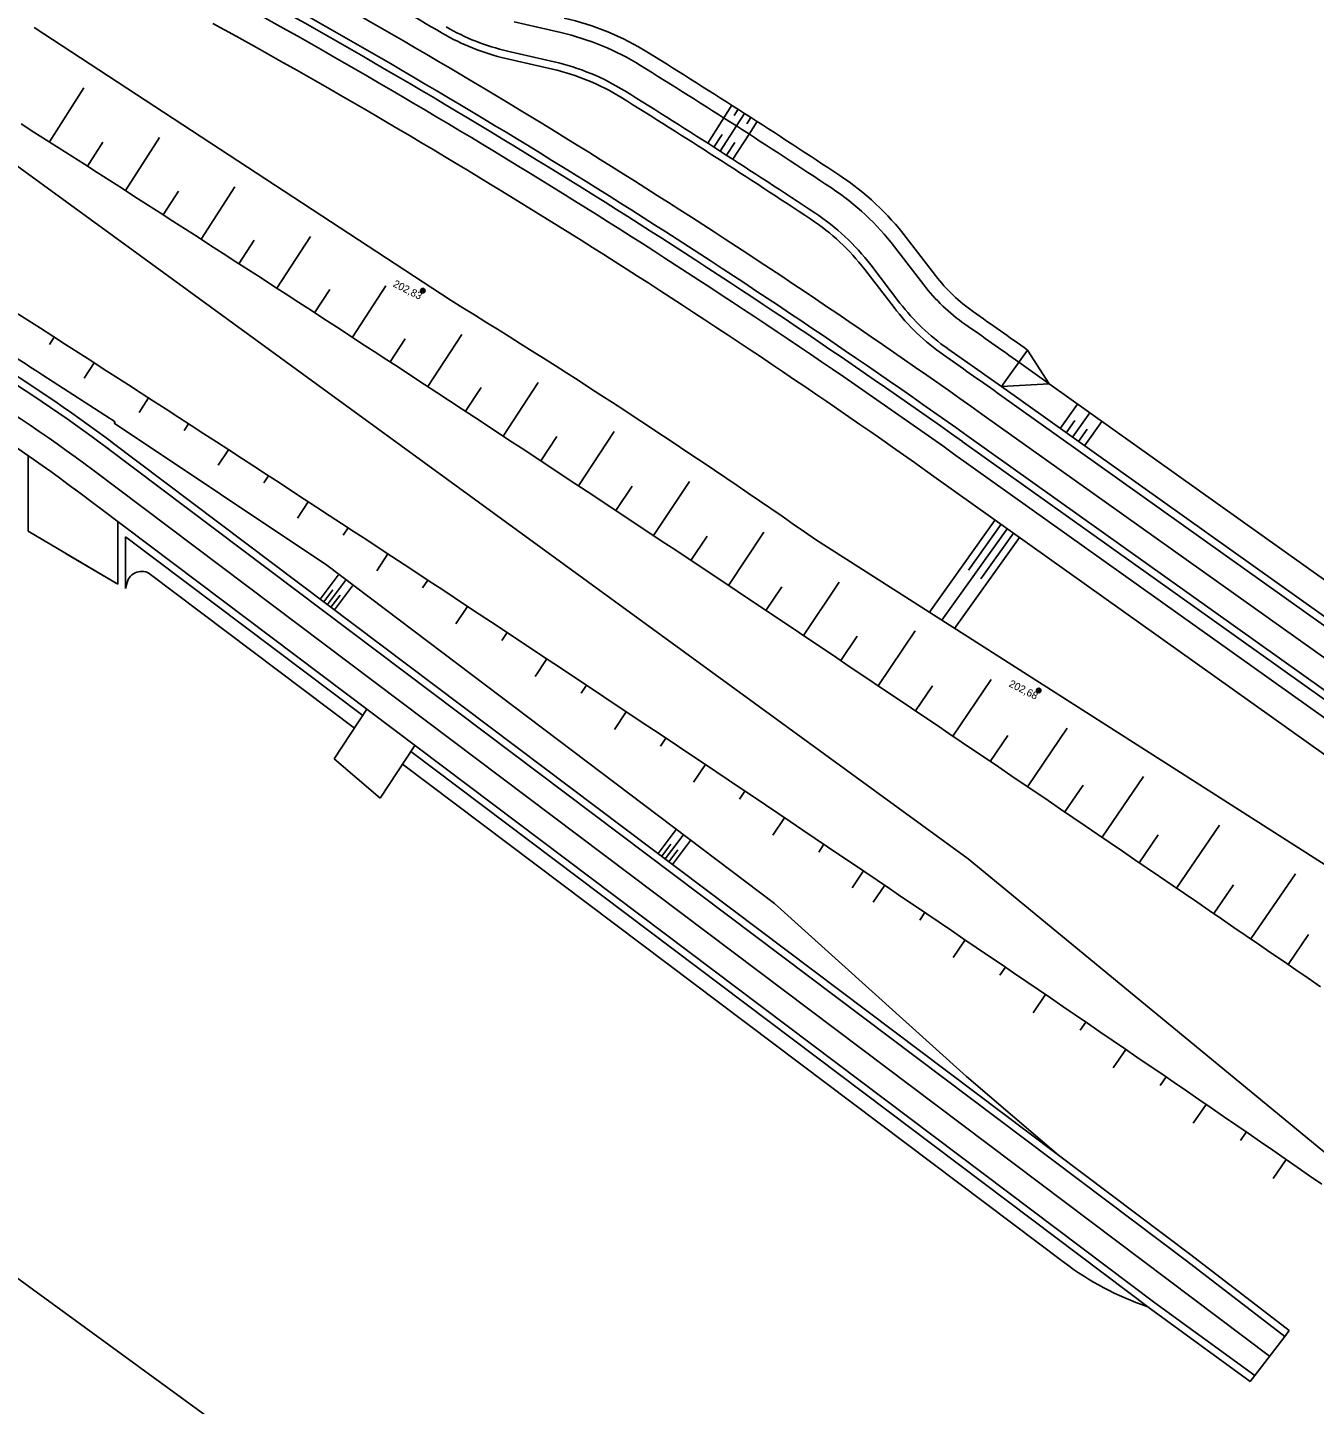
# Model space of a CAD drawing. Extents: x -551750 to -547457, y -1150683 to -1148508.
# Drawn here: x -550268.9 to -550183, y -1149131.6 to -1149039.7 of the extents above; entities that cross this region are included whole.
import ezdxf

# ---------------------------------------------------------------- set-up
doc = ezdxf.new("R2010")
doc.units = 0
for name, color, linetype in [('SO221815_VYSKOPIS', 7, 'Continuous'), ('u_ochranne_pasmo_CD', 7, 'Continuous'), ('u_trat navrh', 7, 'Continuous')]:
    doc.layers.add(name, color=color, linetype=linetype)

# ---------------------------------------------------------------- blocks, each defined once
blk = doc.blocks.new('SO221824_VYSKOPIS')
at = {"layer": 'SO221815_VYSKOPIS'}
for p, q in [((0.123, -0.085), (-0.123, 0.085)), ((0.086, 0.123), (-0.086, -0.123)), ((0.086, 0.123), (0, 0)), ((0, 0), (0.123, -0.085))]:
    blk.add_line(p, q, dxfattribs=at)
blk.add_lwpolyline([(-0.086, -0.123), (0, 0), (-0.123, 0.085)], dxfattribs=at)
blk.add_circle((0, 0), 0.15, dxfattribs=at)
for start, end in [(145.36204, 235.15382), (325.36204, 55.15382)]:
    blk.add_arc((0, 0), 0.15, start, end, dxfattribs=at)

msp = doc.modelspace()

# ---------------------------------------------------------------- linework, layer by layer
at = {"layer": 'u_ochranne_pasmo_CD'}
for points in [[(-551198.31, -1148574.135), (-551162.456, -1148570.351), (-551130.346, -1148568.572), (-551092.366, -1148568.394), (-551061.857, -1148569.283), (-551024.854, -1148573.108), (-550994.968, -1148578.178), (-550959.389, -1148587.695), (-550931.815, -1148595.923), (-550912.514, -1148602.683), (-550895.525, -1148609.665), (-550856.329, -1148625.775), (-550813.026, -1148648.936), (-550764.505, -1148678.6), (-550612.938, -1148787.027), (-550541.958, -1148842.175), (-550442.336, -1148912.265), (-550342.715, -1148992.318), (-550298.516, -1149027.836), (-550206.092, -1149095.142), (-550118.211, -1149167.545), (-550033.177, -1149228.919)], [(-551192.012, -1148633.804), (-551157.645, -1148630.176), (-551128.545, -1148628.564), (-551093.1, -1148628.398), (-551065.821, -1148629.193), (-551032.965, -1148632.589), (-551007.766, -1148636.864), (-550975.723, -1148645.436), (-550950.32, -1148653.016), (-550933.849, -1148658.784), (-550881.948, -1148680.115), (-550842.848, -1148701.028), (-550797.651, -1148728.66), (-550648.813, -1148835.135), (-550577.646, -1148890.428), (-550478.427, -1148960.235), (-550334.988, -1149075.499), (-550242.861, -1149142.589), (-550154.882, -1149215.073), (-550068.292, -1149277.57)]]:
    msp.add_lwpolyline(points, dxfattribs=at)
at = {"layer": 'u_trat navrh'}
for p, q in [((-550268.438, -1149039.663), (-550240.608, -1149057.892)), ((-550236.403, -1149039.288), (-550233.28, -1149040.005)), ((-550236.962, -1149041.725), (-550233.839, -1149042.442)), ((-550236.851, -1149041.237), (-550233.727, -1149041.954)), ((-550267.429, -1149047.3), (-550265.128, -1149043.696)), ((-550222.407, -1149045.694), (-550221.868, -1149044.851)), ((-550221.714, -1149045.543), (-550221.445, -1149045.122)), ((-550221.561, -1149046.235), (-550221.021, -1149045.393)), ((-550223.483, -1149047.379), (-550222.407, -1149045.694)), ((-550222.641, -1149047.918), (-550221.561, -1149046.235)), ((-550220.868, -1149046.086), (-550220.598, -1149045.665)), ((-550220.717, -1149046.778), (-550220.175, -1149045.937)), ((-550264.894, -1149048.92), (-550263.865, -1149047.312)), ((-550262.361, -1149050.542), (-550260.087, -1149046.998)), ((-550223.062, -1149047.648), (-550222.523, -1149046.806)), ((-550222.221, -1149048.188), (-550221.68, -1149047.347)), ((-550221.8, -1149048.459), (-550220.717, -1149046.778)), ((-550259.83, -1149052.168), (-550258.811, -1149050.584)), ((-550257.301, -1149053.797), (-550255.046, -1149050.3)), ((-550252.249, -1149057.063), (-550250.005, -1149053.602)), ((-550210.222, -1149053.683), (-550208.269, -1149056.224)), ((-550254.774, -1149055.428), (-550253.762, -1149053.863)), ((-550211.015, -1149054.292), (-550209.062, -1149056.833)), ((-550212.601, -1149055.511), (-550210.648, -1149058.052)), ((-550212.997, -1149055.816), (-550211.044, -1149058.357)), ((-550249.726, -1149058.701), (-550248.717, -1149057.149)), ((-550247.205, -1149060.341), (-550244.964, -1149056.903)), ((-550242.168, -1149063.631), (-550239.896, -1149060.163)), ((-550267.112, -1149060.326), (-550267.43, -1149060.822)), ((-550244.685, -1149061.985), (-550243.677, -1149060.441)), ((-550264.45, -1149062.038), (-550265.117, -1149063.073)), ((-550202.131, -1149061.188), (-550203.872, -1149063.631)), ((-550200.675, -1149063.452), (-550202.711, -1149062.002)), ((-550200.675, -1149063.452), (-550202.131, -1149061.188)), ((-550263.038, -1149065.972), (-550267.87, -1149062.869)), ((-550239.653, -1149065.281), (-550238.611, -1149063.695)), ((-550237.139, -1149066.933), (-550234.792, -1149063.366)), ((-550200.675, -1149063.452), (-550203.872, -1149063.631)), ((-550179.601, -1149080.918), (-550203.872, -1149063.631)), ((-550178.522, -1149079.231), (-550200.675, -1149063.452)), ((-550260.806, -1149064.389), (-550261.448, -1149065.35)), ((-550204.162, -1149064.038), (-550115.928, -1149126.867)), ((-550199.949, -1149066.425), (-550198.788, -1149064.796)), ((-550205.177, -1149065.464), (-550087.554, -1149149.22)), ((-550199.134, -1149067.005), (-550197.974, -1149065.376)), ((-550263.1, -1149066.076), (-550263.038, -1149065.972)), ((-550248.899, -1149075.545), (-550263.1, -1149066.076)), ((-550258.138, -1149066.116), (-550258.437, -1149066.565)), ((-550232.117, -1149070.246), (-550229.728, -1149066.633)), ((-550199.541, -1149066.715), (-550198.961, -1149065.901)), ((-550198.727, -1149067.295), (-550198.147, -1149066.481)), ((-550198.32, -1149067.585), (-550197.159, -1149065.956)), ((-550191.222, -1149121.587), (-550263.321, -1149067.293)), ((-550234.627, -1149068.588), (-550233.56, -1149066.97)), ((-550206.192, -1149066.889), (-550088.569, -1149150.645)), ((-550268.859, -1149073.287), (-550268.859, -1149068.233)), ((-550191.523, -1149121.986), (-550263.622, -1149067.692)), ((-550255.471, -1149067.847), (-550256.159, -1149068.877)), ((-550144.163, -1149112.9), (-550207.062, -1149068.111)), ((-550185.975, -1149128.354), (-550264.542, -1149069.19)), ((-550252.807, -1149069.581), (-550253.125, -1149070.058)), ((-550229.609, -1149071.906), (-550228.53, -1149070.278)), ((-550227.103, -1149073.569), (-550224.706, -1149069.961)), ((-550140.946, -1149117.646), (-550208.222, -1149069.74)), ((-550193.628, -1149124.782), (-550265.728, -1149070.488)), ((-550250.145, -1149071.318), (-550250.869, -1149072.404)), ((-550262.859, -1149076.817), (-550262.859, -1149072.648)), ((-550247.485, -1149073.059), (-550247.818, -1149073.558)), ((-550204.299, -1149072.534), (-550208.685, -1149078.692)), ((-550203.892, -1149072.824), (-550206.078, -1149075.893)), ((-550268.859, -1149073.287), (-550262.859, -1149076.821)), ((-550246.507, -1149085.588), (-550262.359, -1149073.65)), ((-550262.359, -1149077.115), (-550262.359, -1149073.65)), ((-550224.598, -1149075.235), (-550223.523, -1149073.621)), ((-550222.095, -1149076.903), (-550219.725, -1149073.352)), ((-550166.235, -1149105.784), (-550216.282, -1149073.844)), ((-550203.485, -1149073.114), (-550207.841, -1149079.231)), ((-550202.67, -1149073.694), (-550206.997, -1149079.769)), ((-550203.077, -1149073.404), (-550205.249, -1149076.452)), ((-550262.859, -1149076.821), (-550266.31, -1149074.788)), ((-550244.828, -1149074.803), (-550245.58, -1149075.932)), ((-550219.029, -1149098.143), (-550248.899, -1149075.545)), ((-550262.359, -1149077.115), (-550262.243, -1149076.698)), ((-550247.058, -1149086.425), (-550260.678, -1149076.168)), ((-550248.148, -1149076.215), (-550249.351, -1149077.813)), ((-550247.669, -1149076.576), (-550248.872, -1149078.174)), ((-550242.172, -1149076.55), (-550242.516, -1149077.065)), ((-550217.094, -1149080.247), (-550214.714, -1149076.695)), ((-550248.51, -1149077.195), (-550249.111, -1149077.993)), ((-550248.03, -1149077.556), (-550248.632, -1149078.354)), ((-550247.189, -1149076.937), (-550248.392, -1149078.535)), ((-550219.594, -1149078.574), (-550218.539, -1149076.997)), ((-550239.518, -1149078.3), (-550240.291, -1149079.459)), ((-550236.867, -1149080.053), (-550237.217, -1149080.579)), ((-550214.596, -1149081.923), (-550213.506, -1149080.3)), ((-550212.1, -1149083.601), (-550209.634, -1149079.937)), ((-550234.217, -1149081.809), (-550235.001, -1149082.986)), ((-550207.112, -1149086.964), (-550204.554, -1149083.179)), ((-550231.569, -1149083.568), (-550231.924, -1149084.1)), ((-550209.605, -1149085.281), (-550208.475, -1149083.606)), ((-550248.412, -1149088.482), (-550246.231, -1149085.17)), ((-550228.923, -1149085.33), (-550229.712, -1149086.513)), ((-550202.13, -1149090.336), (-550199.474, -1149086.421)), ((-550245.342, -1149091.093), (-550243.029, -1149087.581)), ((-550226.28, -1149087.095), (-550226.634, -1149087.627)), ((-550204.62, -1149088.649), (-550203.447, -1149086.917)), ((-550245.342, -1149091.093), (-550248.412, -1149088.482)), ((-550193.929, -1149125.181), (-550243.305, -1149087.999)), ((-550199.688, -1149122.097), (-550243.856, -1149088.836)), ((-550223.637, -1149088.863), (-550224.423, -1149090.04)), ((-550199.641, -1149092.026), (-550198.423, -1149090.233)), ((-550197.154, -1149093.717), (-550194.394, -1149089.663)), ((-550220.997, -1149090.633), (-550221.349, -1149091.16)), ((-550218.359, -1149092.406), (-550219.133, -1149093.568)), ((-550225.588, -1149093.204), (-550226.791, -1149094.801)), ((-550192.183, -1149097.107), (-550189.313, -1149092.906)), ((-550225.95, -1149094.183), (-550226.552, -1149094.982)), ((-550225.109, -1149093.565), (-550226.312, -1149095.162)), ((-550224.63, -1149093.925), (-550225.833, -1149095.523)), ((-550215.722, -1149094.182), (-550216.067, -1149094.699)), ((-550194.668, -1149095.411), (-550193.401, -1149093.554)), ((-550225.471, -1149094.544), (-550226.072, -1149095.343)), ((-550213.087, -1149095.96), (-550213.844, -1149097.095)), ((-550211.666, -1149096.921), (-550212.424, -1149098.041)), ((-550189.7, -1149098.805), (-550188.383, -1149096.88)), ((-550187.218, -1149100.504), (-550184.232, -1149096.148)), ((-550206.195, -1149109.686), (-550219.029, -1149098.143)), ((-550208.978, -1149098.741), (-550209.327, -1149099.257)), ((-550206.292, -1149100.564), (-550207.085, -1149101.732)), ((-550184.738, -1149102.206), (-550183.367, -1149100.21)), ((-550203.607, -1149102.389), (-550203.971, -1149102.924)), ((-550200.924, -1149104.217), (-550201.746, -1149105.422)), ((-550198.242, -1149106.047), (-550198.617, -1149106.596)), ((-550195.562, -1149107.879), (-550196.407, -1149109.113)), ((-550200.065, -1149114.927), (-550206.195, -1149109.686)), ((-550192.884, -1149109.714), (-550193.268, -1149110.274)), ((-550190.207, -1149111.551), (-550191.067, -1149112.803)), ((-550187.532, -1149113.39), (-550187.921, -1149113.957)), ((-550184.858, -1149115.232), (-550185.728, -1149116.494)), ((-550184.655, -1149126.638), (-550191.218, -1149121.59)), ((-550184.96, -1149127.034), (-550191.523, -1149121.986)), ((-550194.097, -1149125.055), (-550194.159, -1149125.034)), ((-550187.255, -1149130.039), (-550193.922, -1149125.186)), ((-550186.961, -1149129.635), (-550193.628, -1149124.782)), ((-550184.96, -1149127.034), (-550186.961, -1149129.635)), ((-550184.96, -1149127.034), (-550184.655, -1149126.638)), ((-550186.961, -1149129.635), (-550187.266, -1149130.031))]:
    msp.add_line(p, q, dxfattribs=at)
for points in [[(-550269.311, -1149046.101), (-550268.466, -1149046.639), (-550267.622, -1149047.177), (-550266.778, -1149047.716), (-550265.934, -1149048.255), (-550265.09, -1149048.794), (-550264.247, -1149049.334), (-550263.404, -1149049.874), (-550262.561, -1149050.414), (-550261.718, -1149050.955), (-550260.875, -1149051.496), (-550260.033, -1149052.038), (-550259.191, -1149052.579), (-550258.349, -1149053.121), (-550257.507, -1149053.664), (-550256.665, -1149054.207), (-550255.824, -1149054.75), (-550254.983, -1149055.293), (-550254.142, -1149055.837), (-550253.301, -1149056.381), (-550252.461, -1149056.925), (-550251.621, -1149057.47), (-550250.781, -1149058.015), (-550249.941, -1149058.561), (-550249.102, -1149059.106), (-550248.262, -1149059.652), (-550247.423, -1149060.199), (-550246.584, -1149060.746), (-550245.746, -1149061.293), (-550244.907, -1149061.84), (-550244.069, -1149062.388), (-550243.231, -1149062.936), (-550242.393, -1149063.484), (-550241.555, -1149064.033), (-550240.718, -1149064.582), (-550239.881, -1149065.131), (-550239.044, -1149065.68), (-550238.207, -1149066.23), (-550237.371, -1149066.781), (-550236.534, -1149067.331), (-550235.698, -1149067.882), (-550234.862, -1149068.433), (-550234.026, -1149068.984), (-550233.191, -1149069.536), (-550232.356, -1149070.088), (-550231.521, -1149070.64), (-550230.686, -1149071.193), (-550229.851, -1149071.746), (-550229.016, -1149072.299), (-550228.182, -1149072.852), (-550227.348, -1149073.406), (-550226.514, -1149073.96), (-550225.68, -1149074.515), (-550224.847, -1149075.069), (-550224.014, -1149075.624), (-550223.18, -1149076.179), (-550222.348, -1149076.735), (-550221.515, -1149077.29), (-550220.682, -1149077.846), (-550219.85, -1149078.403), (-550219.018, -1149078.959), (-550218.186, -1149079.516), (-550217.354, -1149080.073), (-550216.522, -1149080.63), (-550215.691, -1149081.188), (-550214.86, -1149081.746), (-550214.029, -1149082.304), (-550213.198, -1149082.862), (-550212.367, -1149083.421), (-550211.536, -1149083.98), (-550210.706, -1149084.539), (-550209.876, -1149085.099), (-550209.046, -1149085.658), (-550208.216, -1149086.218), (-550207.387, -1149086.778), (-550206.557, -1149087.339), (-550205.728, -1149087.899), (-550204.899, -1149088.46), (-550204.07, -1149089.021), (-550203.241, -1149089.583), (-550202.413, -1149090.144), (-550201.584, -1149090.706), (-550200.756, -1149091.268), (-550199.928, -1149091.831), (-550199.1, -1149092.393), (-550198.272, -1149092.956), (-550197.445, -1149093.519), (-550196.617, -1149094.083), (-550195.79, -1149094.646), (-550194.963, -1149095.21), (-550194.136, -1149095.774), (-550193.309, -1149096.338), (-550192.482, -1149096.902), (-550191.656, -1149097.467), (-550190.83, -1149098.032), (-550190.004, -1149098.597), (-550189.178, -1149099.162), (-550188.352, -1149099.728), (-550187.526, -1149100.293), (-550186.7, -1149100.859), (-550185.875, -1149101.425), (-550185.05, -1149101.992), (-550184.225, -1149102.558), (-550183.4, -1149103.125), (-550182.575, -1149103.692)], [(-550269.714, -1149058.658), (-550268.873, -1149059.196), (-550268.032, -1149059.735), (-550267.192, -1149060.275), (-550266.352, -1149060.815), (-550265.511, -1149061.355), (-550264.672, -1149061.895), (-550263.832, -1149062.436), (-550262.993, -1149062.977), (-550262.153, -1149063.519), (-550261.314, -1149064.06), (-550260.476, -1149064.603), (-550259.637, -1149065.145), (-550258.799, -1149065.688), (-550257.961, -1149066.231), (-550257.123, -1149066.774), (-550256.285, -1149067.318), (-550255.448, -1149067.862), (-550254.61, -1149068.407), (-550253.773, -1149068.952), (-550252.936, -1149069.497), (-550252.1, -1149070.042), (-550251.263, -1149070.588), (-550250.427, -1149071.134), (-550249.591, -1149071.681), (-550248.755, -1149072.227), (-550247.92, -1149072.775), (-550247.084, -1149073.322), (-550246.249, -1149073.87), (-550245.414, -1149074.418), (-550244.579, -1149074.966), (-550243.745, -1149075.515), (-550242.91, -1149076.064), (-550242.076, -1149076.613), (-550241.242, -1149077.163), (-550240.408, -1149077.713), (-550239.574, -1149078.263), (-550238.741, -1149078.813), (-550237.908, -1149079.364), (-550237.075, -1149079.915), (-550236.242, -1149080.467), (-550235.409, -1149081.019), (-550234.577, -1149081.571), (-550233.744, -1149082.123), (-550232.912, -1149082.676), (-550232.08, -1149083.228), (-550231.249, -1149083.782), (-550230.417, -1149084.335), (-550229.586, -1149084.889), (-550228.755, -1149085.443), (-550227.924, -1149085.997), (-550227.093, -1149086.552), (-550226.262, -1149087.107), (-550225.432, -1149087.662), (-550224.601, -1149088.218), (-550223.771, -1149088.773), (-550222.941, -1149089.329), (-550222.112, -1149089.886), (-550221.282, -1149090.442), (-550220.453, -1149090.999), (-550219.624, -1149091.556), (-550218.794, -1149092.113), (-550217.966, -1149092.671), (-550217.137, -1149093.229), (-550216.308, -1149093.787), (-550215.48, -1149094.345), (-550214.652, -1149094.904), (-550213.824, -1149095.463), (-550212.996, -1149096.022), (-550212.168, -1149096.582), (-550211.341, -1149097.141), (-550210.513, -1149097.701), (-550209.686, -1149098.261), (-550208.859, -1149098.822), (-550208.032, -1149099.383), (-550207.205, -1149099.944), (-550206.379, -1149100.505), (-550205.552, -1149101.066), (-550204.726, -1149101.628), (-550203.9, -1149102.19), (-550203.074, -1149102.752), (-550202.248, -1149103.314), (-550201.423, -1149103.877), (-550200.597, -1149104.44), (-550199.772, -1149105.003), (-550199.28, -1149105.338), (-550198.946, -1149105.566), (-550198.121, -1149106.129), (-550197.296, -1149106.693), (-550196.472, -1149107.257), (-550195.647, -1149107.821), (-550194.823, -1149108.386), (-550193.998, -1149108.95), (-550193.174, -1149109.515), (-550192.35, -1149110.08), (-550191.526, -1149110.646), (-550190.702, -1149111.211), (-550189.879, -1149111.777), (-550189.055, -1149112.343), (-550188.232, -1149112.909), (-550187.409, -1149113.475), (-550186.586, -1149114.042), (-550185.763, -1149114.608), (-550184.94, -1149115.175), (-550184.117, -1149115.743), (-550183.295, -1149116.31), (-550182.472, -1149116.877)], [(-550102.809, -1149141.119), (-550132.807, -1149119.759), (-550142.581, -1149112.799), (-550206.482, -1149067.297)]]:
    msp.add_lwpolyline(points, dxfattribs=at)
for centre, radius, start, end in [((-550495.243, -1149472.725), 501.75, 59.58162, 61.14938), ((-550495.243, -1149472.725), 500, 54.5401, 61.14938), ((-550495.243, -1149472.725), 498.25, 54.5401, 61.14938), ((-550495.243, -1149472.725), 497.75, 54.5401, 61.14938), ((-550495.243, -1149472.725), 496.75, 54.5401, 61.14938), ((-550237.194, -1149057.061), 18.5, 58.1674, 77.07566), ((-550495.243, -1149472.725), 494.75, 54.5401, 61.14938), ((-550233.608, -1149027.105), 14.5, 239.58162, 257.07566), ((-550237.194, -1149057.061), 17.5, 58.1674, 77.07566), ((-550233.608, -1149027.105), 15, 239.58162, 257.07566), ((-550495.243, -1149472.725), 507.75, 56.45532, 58.1674), ((-550237.194, -1149057.061), 15, 58.1674, 77.07566), ((-550237.194, -1149057.061), 15.5, 58.1674, 77.07566), ((-550495.243, -1149472.725), 506.75, 56.45532, 58.1674), ((-550495.243, -1149472.725), 504.25, 56.45532, 58.1674), ((-550495.243, -1149472.725), 504.75, 56.45532, 58.1674), ((-550224.89, -1149064.957), 18.5, 37.54705, 56.45532), ((-550224.89, -1149064.957), 17.5, 37.54705, 56.45532), ((-550224.89, -1149064.957), 15, 37.54705, 56.45532), ((-550224.89, -1149064.957), 15.5, 37.54705, 56.45532), ((-550324.697, -1149149.073), 103.25, 56.60678, 65.00097), ((-550324.697, -1149149.073), 102.25, 53.0187, 65.25784), ((-550199.151, -1149049.215), 11.5, 217.54705, 235.04109), ((-550324.697, -1149149.073), 100, 53.0187, 66.44936), ((-550324.697, -1149149.073), 101.75, 53.0187, 65.25784), ((-550199.151, -1149049.215), 12.5, 217.54705, 235.04109), ((-550495.243, -1149472.725), 486.75, 55.03258, 58.45727), ((-550199.151, -1149049.215), 15, 217.54705, 235.04109), ((-550199.151, -1149049.215), 14.5, 217.54705, 235.04109), ((-550324.697, -1149149.073), 98.25, 53.0187, 66.44936), ((-550495.243, -1149472.725), 505.25, 54.5401, 55.04109), ((-550495.243, -1149472.725), 504.25, 54.5401, 55.04109), ((-550495.243, -1149472.725), 502.25, 54.5401, 55.04109), ((-550495.243, -1149472.725), 501.75, 54.5401, 55.04109), ((-550261.28, -1149076.967), 1, 53.0187, 164.41175), ((-550187.656, -1149106.12), 20, 233.0187, 251.02813)]:
    msp.add_arc(centre, radius, start, end, dxfattribs=at)

# ---------------------------------------------------------------- block references
at = {"layer": 'u_trat navrh', "rotation": -31.851985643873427}
for p in [(-550242.503, -1149057.224), (-550201.385, -1149083.921)]:
    msp.add_blockref('SO221824_VYSKOPIS', p, dxfattribs=at)

# ---------------------------------------------------------------- texts
at = {"layer": 'u_trat navrh'}
for s, p in [('202,83', (-550244.538, -1149056.929)), ('202,68', (-550203.419, -1149083.625))]:
    msp.add_text(s, height=0.5, rotation=333.25678, dxfattribs=at).set_placement(p)

doc.saveas('drawing.dxf')
